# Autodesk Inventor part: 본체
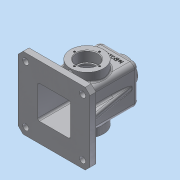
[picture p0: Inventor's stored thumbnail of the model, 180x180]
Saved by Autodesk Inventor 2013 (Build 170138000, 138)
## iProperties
Created: 2018-10
Part Number: 본체
Material: 알루미늄 6061
Document SubType Name: Modeling
Designer: Administrator
Density: 2.71 g/cm^3
Mass: 797.324 g
Surface Area: 900.131 cm^2
Volume: 294.215 cm^3
Author: Administrator
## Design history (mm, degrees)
sketch "스케치1"
  geometry: L1 (32.5, 32.5)-(-32.5, 32.5); L2 (-32.5, 32.5)-(-32.5, -32.5); L3 (-32.5, -32.5)-(32.5, -32.5); L4 (32.5, -32.5)-(32.5, 32.5); L5 (32.5, 32.5)-(-32.5, -32.5); L6 (-32.5, 32.5)-(32.5, -32.5); 1 further point
  constraints: 12 end point, 2 midpoint, 2 parallel, 1 horizontal, 1 perpendicular
  dimensions: "d0" = 65 distance of L3.end L2.end; "d1" = 65 distance of L2.end L1.end
extrude "돌출1" new body sketch "스케치1" distance "d2" = 100; taper "d3" = 0 deg
node "작업 평면1"
sketch "스케치3"
  geometry: L1 (60, 60)-(-60, 60); L2 (-60, 60)-(-60, -60); L3 (-60, -60)-(60, -60); L4 (60, -60)-(60, 60); L5 (60, 60)-(-60, -60); L6 (-60, 60)-(60, -60); 3 further points
  constraints: 12 end point, 3 midpoint, 2 parallel, 1 coincident, 1 horizontal, 1 perpendicular
  dimensions: "d5" = 120 distance of L3.end L2.end; "d6" = 120 distance of L2.end L1.end
extrude "돌출2" join sketch "스케치3" distance "d7" = 10; taper "d8" = 0 deg
node "작업 평면2"
sketch "스케치16"
  geometry: C1 r 20 at (0, 0); 1 further point
  constraints: 1 centre point, 1 coincident
  dimensions: "d105" = 40 diameter of C1
extrude "돌출8" join sketch "스케치16" stored distance "d106" = 3; taper "d107" = 7 deg
sketch "스케치5"
  geometry: L1 (0, 0)-(0, -100) reference; L2 (92.5, -110)-(-27.5, -110) reference; C1 r 27.5 at (32.5, -55); 1 further point
  constraints: 1 centre point
  dimensions: "d12" = 55 diameter of C1; "d13" = 55 distance from line of L2 C1.centre; "d14" = 32.5 distance from line of C1.centre L1
extrude "돌출4" join sketch "스케치5" distance "d15" = 15; taper "d16" = 0 deg
sketch "스케치7"
  geometry: L1 (-27.5, -27.5)-(27.5, -27.5); L2 (27.5, -27.5)-(27.5, 27.5); L3 (27.5, 27.5)-(-27.5, 27.5); L4 (-27.5, 27.5)-(-27.5, -27.5); L5 (-27.5, -27.5)-(27.5, 27.5); L6 (27.5, -27.5)-(-27.5, 27.5); 1 further point
  constraints: 12 end point, 2 midpoint, 2 parallel, 1 horizontal, 1 perpendicular
  dimensions: "d17" = 55 distance of L3.end L2.end; "d18" = 55 distance of L2.end L1.end
extrude "돌출5" cut sketch "스케치7" distance "d19" = 105; taper "d20" = 0 deg
sketch "스케치8"
  geometry: C1 r 27.5 at (0, 0) reference; C2 r 17.5 at (0, 0); 1 further point
  constraints: 1 centre point, 1 coincident
  dimensions: "d21" = 35 diameter of C2
extrude "돌출6" cut sketch "스케치8" distance "d22" = 17; taper "d23" = 0 deg
sketch "스케치9"
  geometry: C1 r 17.5 at (0, 0) reference; C2 r 15 at (0, 0); 1 further point
  constraints: 1 centre point, 1 coincident
  dimensions: "d24" = 30 diameter of C2
extrude "돌출7" cut sketch "스케치9" distance "d25" = 3; taper "d26" = 0 deg
chamfer "모따기1" distance "d27" = 1; stored, may be unused: second distance "d28" = 2, angle "d29" = 45 deg
sketch "스케치10"
  geometry: L1 (-60, -100)-(-60, -110) reference; L2 (60, -100)-(-60, -100) reference; L3 (32.5, -100)-(60, -100) reference; L4 (60, -100)-(60, -110) reference; L5 (60, -110)-(27.5, -110) reference; L6 (27.5, -110)-(27.5, -5) reference; L7 (27.5, -5)-(-27.5, -5) reference; L8 (-27.5, -5)-(-27.5, -110) reference; L9 (-27.5, -110)-(-60, -110) reference; L10 (-60, -110)-(-60, -100) reference; L11 (-60, -100)-(-32.5, -100) reference; L12 (-32.5, -100)-(-32.5, 0) reference; L13 (-32.5, 0)-(-21.228, 0) reference; L14 (21.228, 0)-(32.5, 0) reference; L15 (32.5, 0)-(32.5, -100) reference; L16 (-48, -100)-(-38.544, -46.373); L17 (-21.228, 0)-(-20, 10) reference; L18 (-20, 10)-(20, 10) reference; L19 (20, 10)-(21.228, 0) reference; 1 further point
  constraints: 2 end point, 1 point on line
  dimensions: "d36" = 12 distance from line of L1 L16.start; "d37" = 10 deg angle of L1 L16
feature "리브1" sketch "스케치10" dims "d38" = 1, "d39" = 10, "d40" = 0, "d41" = 0, "d42" = 1, "d43" = 1
chamfer "모따기2" distance "d44" = 8; stored, may be unused: second distance "d45" = 2, angle "d46" = 45 deg
sketch "스케치12"
  geometry: L1 (-40, 27.5)-(-40, 30.5) reference; L2 (-40, 30.5)-(-37.5, 30.5) reference; L3 (-37.5, 30.5)-(-37.5, 46.5) reference; L4 (-37.5, 46.5)-(-36.5, 47.5) reference; L5 (-36.5, 47.5)-(-27.5, 47.5) reference; L6 (-27.5, 47.5)-(-27.5, 32.5) reference; L7 (-27.5, 32.5)-(0, 32.5) reference; L8 (0, 32.5)-(0, 21.228) reference; L9 (0, -21.228)-(0, -32.5) reference; L10 (0, -32.5)-(-27.5, -32.5) reference; L11 (-82.5, -47.5)-(-82.5, -32.5) reference; L12 (-72.5, -47.5)-(-82.5, -47.5) reference; L13 (-72.5, -30.5)-(-72.5, -47.5) reference; L14 (-37.5, -47.5)-(-37.5, -30.5) reference; L15 (-27.5, -47.5)-(-37.5, -47.5) reference; L16 (-27.5, -32.5)-(-27.5, -47.5) reference; L17 (-82.5, -32.5)-(-100, -32.5) reference; L18 (-100, -32.5)-(-100, -60) reference; L19 (-100, -60)-(-110, -60) reference; L20 (-110, -60)-(-110, -27.5) reference; L21 (-110, -27.5)-(-70, -27.5) reference; L22 (-5, -27.5)-(-5, 27.5) reference; L23 (-5, 27.5)-(-40, 27.5) reference; L24 (-70, 30.5)-(-70, 27.5) reference; L25 (-70, 27.5)-(-110, 27.5) reference; L26 (-110, 27.5)-(-110, 60) reference; L27 (-110, 60)-(-100, 60) reference; L28 (-100, 60)-(-100, 32.5) reference; L29 (-100, 32.5)-(-82.5, 32.5) reference; L30 (-82.5, 32.5)-(-82.5, 47.5) reference; L31 (-82.5, 47.5)-(-73.5, 47.5) reference; L32 (-73.5, 47.5)-(-72.5, 46.5) reference; L33 (-72.5, 46.5)-(-72.5, 30.5) reference; L34 (-72.5, 30.5)-(-70, 30.5) reference; L35 (-85.736, -42.5)-(-97.258, -42.5); L36 (-70, -27.5)-(-70, -30.5) reference; L37 (-70, -30.5)-(-72.5, -30.5) reference; L38 (-37.5, -30.5)-(-40, -30.5) reference; L39 (-40, -30.5)-(-40, -27.5) reference; L40 (-40, -27.5)-(-5, -27.5) reference; L41 (0, 21.228)-(10, 20) reference; L42 (10, 20)-(10, -20) reference; L43 (10, -20)-(0, -21.228) reference; 1 further point
  constraints: 2 end point, 1 parallel
  dimensions: "d47" = 15 distance between parallel lines of L35 L21
feature "리브2" sketch "스케치12" dims "d48" = 1, "d49" = 6, "d50" = 0, "d51" = 0, "d52" = 1, "d53" = 1
sketch "스케치13"
  geometry: L1 (52, 60)-(-52, 60) reference; L2 (-60, 52)-(-60, -52) reference; L3 (-52, -60)-(52, -60) reference; L4 (60, -52)-(60, 52) reference; 5 further points
  dimensions: "d54" = 95 distance of point (47.5, 47.5) point (-47.5, 47.5); "d56" = 95 distance of point (47.5, -47.5) point (47.5, 47.5); "d57" = 95 distance of point (-47.5, 47.5) point (-47.5, -47.5); "d58" = 12.5 distance from line of L3 point (47.5, -47.5); "d59" = 12.5 distance from line of L1 point (47.5, 47.5); "d60" = 12.5 distance from line of L3 point (-47.5, -47.5); "d61" = 12.5 distance from line of L2 point (-47.5, 47.5); "d62" = 12.5 distance from line of L4 point (47.5, 47.5)
hole "구멍1" sketch "스케치13" at (47.5, 47.5), (-47.5, 47.5), (-47.5, -47.5), (47.5, -47.5) diameter "d63" = 10; stored, may be unused: countersink angle "d67" = 90 deg, drill point angle "d69" = 0 deg; dims "d64" = 6, "d65" = 4, "d66" = 2, "d68" = 8
fillet "모깎기1" dims "d79" = 8
fillet "모깎기2" dims "d80" = 0.3
fillet "모깎기3" dims "d81" = 8
fillet "모깎기4" dims "d82" = 3
fillet "모깎기5" dims "d83" = 3
fillet "모깎기6" dims "d84" = 3
fillet "모깎기7" dims "d85" = 3
fillet "모깎기8" dims "d86" = 1
sketch "스케치14"
  geometry: L1 (84.5, -102)-(-35.5, -102) reference; L2 (-35.5, -102)-(-35.5, -92) reference; L3 (-35.5, -92)-(-4.123, -92) reference; L4 (0, -91)-(21.5, -91) reference; L5 (21.5, -91)-(21.5, -77.352) reference; L6 (0, 0)-(0, -28.834) reference; L7 (0, 0)-(49, 0) reference; L8 (49, 0)-(49, -28.834) reference; L9 (84.5, -92)-(84.5, -102) reference; L10 (53.123, -92)-(84.5, -92) reference; L11 (49, -65.166)-(49, -91) reference; L12 (0, -65.166)-(0, -91) reference; L13 (27.5, -91)-(49, -91) reference; L14 (27.5, -77.352)-(27.5, -91) reference; L15 (5.728, 18)-(43.272, 18) reference; L16 (-8, 0)-(-8, -91) reference; L17 (4.5, 18)-(44.5, 18) reference; C1 r 17.5 at (24.5, -47) reference; A1 r 30.5 centre (24.5, -47) between (0, -65.166) and (21.5, -77.352) reference; A2 r 30.5 centre (24.5, -47) between (49, -28.834) and (0, -28.834) reference; A3 r 30.5 centre (24.5, -47) between (27.5, -77.352) and (49, -65.166) reference; 2 further points
  constraints: 2 vertical alignment, 3 other
  dimensions: "d89" = 32.5 distance from line of L16 point (24.5, -8); "d108" = 26 distance from line of point (24.5, -8) L17
  node "절단 모서리 투영3"
sketch "스케치15" dims "d92" = 42
  geometry: C1 r 27.5 at (0, 0) reference; 3 further points
  constraints: 2 vertical alignment, 1 coincident, 2 other
hole "구멍3" sketch "스케치15" at (0, 21) diameter "d93" = 3.242; stored, may be unused: countersink angle "d97" = 90 deg, drill point angle "d99" = 118 deg; dims "d94" = 8, "d95" = 4, "d96" = 2, "d98" = 10
fillet "모깎기10" dims "d103" = 3
feature "엠보싱2" dims "d109" = 0.5, "d110" = 0
hole "구멍4" diameter "d113" = 22.835; stored, may be unused: countersink angle "d117" = 90 deg, drill point angle "d119" = 0 deg; dims "d111" = 10, "d112" = 10, "d114" = 50, "d115" = 4, "d116" = 2, "d118" = 10
fillet "모깎기11" dims "d120" = 3
chamfer "모따기3" distance "d121" = 1; stored, may be unused: second distance "d122" = 2, angle "d123" = 45 deg
node "솔리드1"
mirror "대칭1"
mirror "대칭2"
mirror "대칭3"
pattern_circular "원형 패턴1" dims angle "d101" = 360 deg
mirror "대칭4"
node "절단 모서리 투영1"
node "절단 모서리 투영2"
